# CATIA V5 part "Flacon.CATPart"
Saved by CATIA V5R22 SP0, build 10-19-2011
Part number: Flacon
Material "Vert": density 7860 kg/m3, Young's modulus 2e+11 Pa, Poisson ratio 0.266
Bounding box of the stored display mesh (mm): x -25 to 25, y -25 to 25, z 0 to 50
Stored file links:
  D:\PER\CAO_PER_MODIF_2025\CAO_PER_pick&place_2024P\Sous_Ensemble_Flacon\Flacon.CATPart
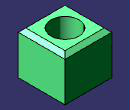
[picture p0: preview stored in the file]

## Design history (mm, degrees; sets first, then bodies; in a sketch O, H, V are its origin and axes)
Body1 (main body), material "Vert"
  Sketch1 on xy-plane, origin (0, 0, 0), H (1, 0, 0), V (0, 1, 0)
    line L1 (25, 25) -> (25, -25)
    line L2 (25, -25) -> (-25, -25)
    line L3 (-25, -25) -> (-25, 25)
    line L4 (-25, 25) -> (25, 25)
    length L1 = 50
    length L2 = 50
    vertical: L1 V, L3 V
    horizontal: L2 H, L4 H
    equidistance: L1 L3 O, L2 L4 O
  Pad1: profile Sketch1, direction (0, 0, 1), length 50
  Sketch2 on end face of Pad1, origin (5.616, -5.616, 50), H (1, 0, 0), V (0, 1, 0)
    point P1 (-5.616, 5.616)
    reference projected line E1 (19.384, -19.384) -> (19.384, 30.616) from edge [face of Pad1 from Sketch1.L1 | end face of Pad1]
    reference projected line E2 (-30.616, -19.384) -> (19.384, -19.384) from edge [face of Pad1 from Sketch1.L2 | end face of Pad1]
    distance P1 E1 = 25
    distance P1 E2 = 25
  Hole1: placed by Sketch2, at (0, 0, 50) direction (0, 0, -1), diameter 30, depth 40
  Chamfer1: length 4, angle 45, on edge [face of Pad1 from Sketch1.L4 | end face of Pad1]; edge [face of Pad1 from Sketch1.L3 | end face of Pad1]; edge [face of Pad1 from Sketch1.L2 | end face of Pad1]; edge [face of Pad1 from Sketch1.L1 | end face of Pad1]; edge [start face of Pad1 | face of Pad1 from Sketch1.L3]; edge [start face of Pad1 | face of Pad1 from Sketch1.L4]; edge [start face of Pad1 | face of Pad1 from Sketch1.L2]; edge [start face of Pad1 | face of Pad1 from Sketch1.L1]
